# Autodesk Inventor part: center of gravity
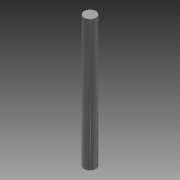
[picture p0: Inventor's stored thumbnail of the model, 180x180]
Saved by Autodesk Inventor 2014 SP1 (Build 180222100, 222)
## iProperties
Created: 2014-04
Part Number: center of gravity
Material: Stainless Steel, 440C
Document SubType Name: Modeling
Designer: BobvH
Density: 7.75 g/cm^3
Appearance: Semi-Polished
Mass: 207183 g
Surface Area: 21127.7 cm^2
Volume: 26733.3 cm^3
Author: BobvH
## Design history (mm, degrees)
sketch "Sketch1"
  geometry: C1 r 90 at (0, 0); 1 further point
  constraints: 1 centre point, 1 coincident
  dimensions: "d0" = 180 diameter of C1
extrude "Extrusion1" new body sketch "Sketch1" distance "d1" = 2000; taper "d2" = 0 deg
workplane "Work Plane1"
sketch "Sketch3"
  geometry: L1 (-88.978, -2)-(88.978, -2); A1 r 89 centre (0, 0) between (-88.978, -2) and (88.978, -2); 1 further point
  constraints: 2 end point, 2 point on circle, 1 centre point, 1 coincident, 1 horizontal
  dimensions: "d6" = 178 diameter of A1; "d7" = 2 distance from line of A1.centre L1
extrude "Extrusion3" cut sketch "Sketch3" stored distance "d8" = 1999; taper "d9" = 0 deg
sketch "Sketch4"
  geometry: 1 further point
sketch "Sketch5"
  geometry: L1 (35.255, 999.957)-(35.255, 1999.957); 1 further point
  constraints: 2 end point, 1 vertical
  dimensions: "d10" = 1000 distance of L1.start L1.end
sketch "Sketch6"
  geometry: L1 (0, 45.255)-(0, 25.255); L2 (10, 35.255)-(-10, 35.255); A1 r 10 centre (0, 35.255) between (0, 25.255) and (10, 35.255); A2 r 10 centre (0, 35.255) between (0, 45.255) and (-10, 35.255); 2 further points
  constraints: 4 end point, 4 point on circle, 2 centre point, 2 midpoint, 1 coincident, 1 perpendicular, 1 vertical
extrude "Extrusion5" join sketch "Sketch6" distance "d18" = 0.5; taper "d19" = 0 deg
sketch "Sketch9"
  geometry: L1 (0, 35.255)-(10, 35.255) reference; L2 (0, 25.255)-(0, 35.255) reference; L3 (0, 35.255)-(-10, 35.255) reference; L4 (0, 45.255)-(0, 35.255) reference; A1 r 10 centre (0, 35.255) between (0, 45.255) and (-10, 35.255) reference; A2 r 10 centre (0, 35.255) between (-10, 35.255) and (0, 25.255); A3 r 10 centre (0, 35.255) between (10, 35.255) and (0, 45.255)
  constraints: 4 end point, 4 point on circle, 2 centre point, 1 coincident
extrude "Extrusion7" cut sketch "Sketch9" distance "d22" = 0.5; taper "d23" = 0 deg
body "Solid1"
